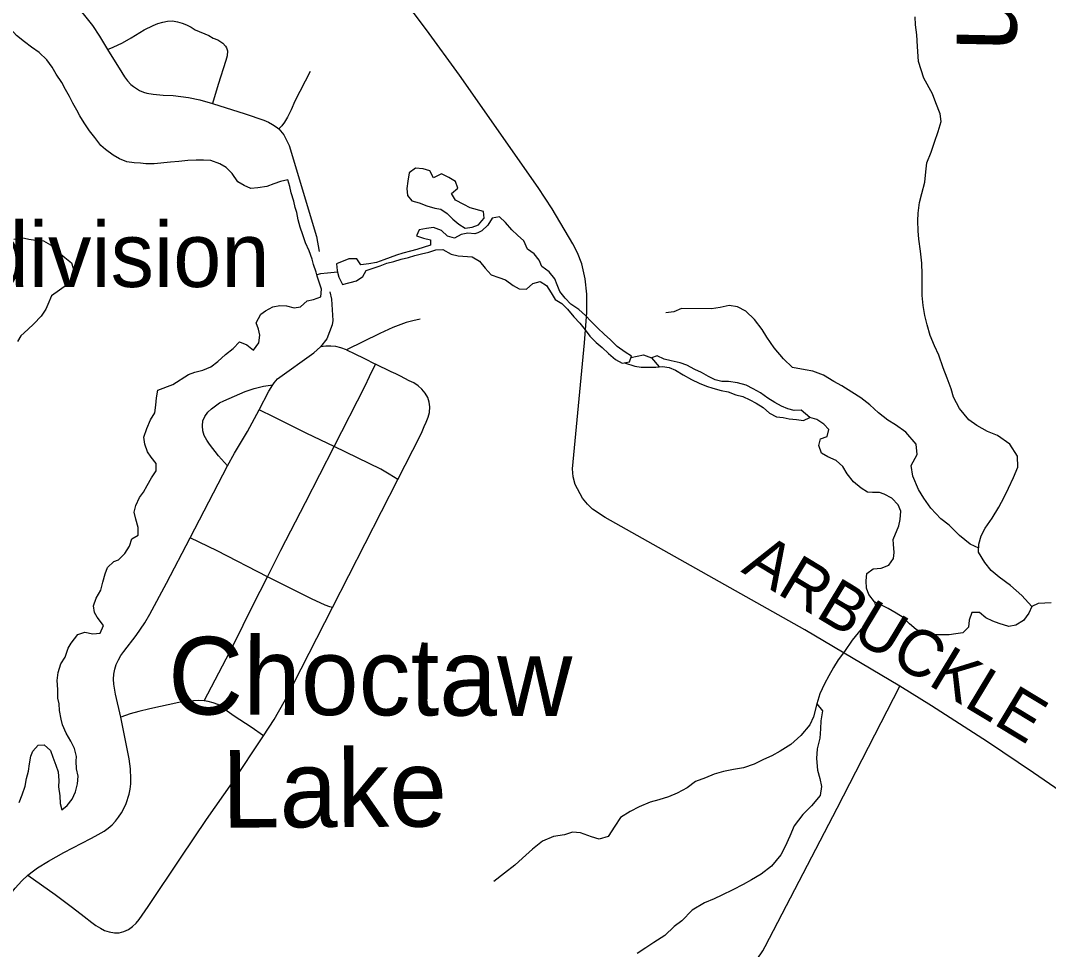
# Model space of a CAD drawing. Extents: x 0 to 36.5, y 0 to 25.3.
# Drawn here: x 5.198 to 6.451, y 18.689 to 19.822 of the extents above; entities that cross this region are included whole.
import ezdxf

# ---------------------------------------------------------------- set-up
doc = ezdxf.new("R2010")
doc.units = 0
for name, color, linetype in [('GM_X_County_Road', 7, 'Continuous'), ('GM_X_County_Road_Text', 7, 'Continuous'), ('GM_X_Major_Lake', 7, 'Continuous'), ('GM_X_Major_Lake_Text', 7, 'Continuous'), ('GM_X_Major_River', 7, 'Continuous'), ('GM_X_Minor_Lake', 7, 'Continuous'), ('GM_X_Minor_River', 7, 'Continuous'), ('GM_X_Minor_River_Text', 7, 'Continuous'), ('GM_X_Township_Road', 7, 'Continuous'), ('GM_X_Unincorporated_Text', 7, 'Continuous')]:
    doc.layers.add(name, color=color, linetype=linetype)

msp = doc.modelspace()

# ---------------------------------------------------------------- linework, layer by layer
at = {"layer": 'GM_X_County_Road'}
for points in [[(6.27, 19.0102), (6.154, 19.0787), (5.9106, 19.2156), (5.8953, 19.2261), (5.8889, 19.2321), (5.8831, 19.2395), (5.874, 19.2561), (5.8715, 19.2656), (5.8706, 19.2751), (5.8855, 19.4287), (5.8883, 19.4658), (5.8884, 19.4882), (5.8862, 19.5068), (5.882, 19.5251), (5.8767, 19.5387), (5.871, 19.5497), (5.8458, 19.5924), (5.8291, 19.6185), (5.7328, 19.7554), (5.6929, 19.8107), (5.6026, 19.9308)], [(6.4783, 18.8731), (6.4329, 18.9045), (6.3767, 18.9421), (6.3084, 18.9862), (6.27, 19.0102)]]:
    msp.add_lwpolyline(points, dxfattribs=at)
at = {"layer": 'GM_X_Major_Lake'}
for points in [[(5.3012, 19.6647), (5.2955, 19.6696), (5.2883, 19.6792), (5.2819, 19.6875), (5.2751, 19.6971), (5.2702, 19.7058), (5.2664, 19.7127), (5.2615, 19.7214), (5.2573, 19.7294), (5.2524, 19.7378), (5.2482, 19.7465), (5.2411, 19.7568), (5.2361, 19.7652), (5.2297, 19.7739), (5.2206, 19.7831), (5.2111, 19.7895), (5.2024, 19.796), (5.1929, 19.8036), (5.1858, 19.8116), (5.1824, 19.8174), (5.1771, 19.8257)], [(5.5237, 19.6276), (5.5145, 19.6258), (5.5066, 19.6227), (5.4982, 19.6197), (5.4872, 19.6178), (5.4784, 19.6171), (5.4705, 19.6206), (5.4625, 19.6251), (5.4557, 19.6354), (5.4485, 19.6426), (5.4409, 19.6472), (5.4299, 19.6514), (5.4208, 19.6518), (5.4117, 19.6515), (5.4018, 19.6511), (5.3908, 19.65), (5.3805, 19.6493), (5.3608, 19.6471), (5.3505, 19.6471), (5.3441, 19.6479), (5.3361, 19.6483), (5.3274, 19.6498), (5.3182, 19.6533), (5.3107, 19.6578), (5.3012, 19.6647)], [(5.5591, 19.5117), (5.5583, 19.5151), (5.5549, 19.5246), (5.5534, 19.531), (5.5496, 19.5413), (5.5451, 19.5508), (5.5421, 19.5607), (5.5387, 19.5698), (5.5364, 19.579), (5.5346, 19.5877), (5.5327, 19.5938), (5.5308, 19.6018), (5.5278, 19.6117), (5.5259, 19.6196), (5.5237, 19.6276)], [(5.1896, 19.5552), (5.1987, 19.5575), (5.2078, 19.5555), (5.2162, 19.554), (5.2257, 19.5532), (5.2344, 19.5486), (5.2423, 19.5406), (5.2518, 19.533), (5.2598, 19.5265), (5.2628, 19.517), (5.262, 19.5083), (5.2536, 19.4992), (5.2452, 19.4931), (5.2353, 19.4863), (5.2308, 19.4757), (5.2285, 19.47), (5.2227, 19.4613), (5.214, 19.4522), (5.2064, 19.445), (5.198, 19.4374), (5.1938, 19.4306)], [(5.2424, 19.0171), (5.2435, 19.0269), (5.247, 19.0372), (5.2523, 19.0455), (5.2558, 19.0566), (5.2596, 19.0626), (5.2676, 19.0732), (5.2763, 19.0759), (5.2858, 19.0739), (5.2949, 19.0747), (5.2988, 19.0842), (5.2912, 19.0941), (5.2878, 19.0998), (5.2867, 19.1081), (5.2901, 19.1173), (5.2958, 19.1271), (5.2982, 19.137), (5.3008, 19.1469), (5.3039, 19.1548), (5.3115, 19.162), (5.3172, 19.1643), (5.3248, 19.1719), (5.3306, 19.181), (5.3336, 19.1897), (5.3412, 19.1942), (5.3413, 19.2037), (5.3383, 19.2136), (5.3364, 19.2224), (5.3383, 19.2303), (5.3429, 19.2402), (5.3475, 19.2467), (5.3521, 19.255), (5.3574, 19.2641), (5.3631, 19.2728), (5.3631, 19.2816), (5.3571, 19.2896), (5.3525, 19.296), (5.3492, 19.3052), (5.348, 19.3139), (5.3519, 19.3245), (5.3561, 19.3348), (5.3614, 19.3435), (5.3626, 19.353), (5.3634, 19.3617), (5.3653, 19.3712), (5.3836, 19.378), (5.4026, 19.3901), (5.4102, 19.3931), (5.4201, 19.3954), (5.4299, 19.3995), (5.4383, 19.406), (5.4475, 19.4147), (5.457, 19.4219), (5.4646, 19.4302), (5.4737, 19.4264), (5.4817, 19.4199), (5.4881, 19.429), (5.4893, 19.4381), (5.4878, 19.4457), (5.4852, 19.4533), (5.4909, 19.464), (5.4966, 19.4678), (5.5054, 19.4727), (5.5137, 19.4745), (5.5221, 19.4741), (5.5312, 19.4715), (5.5392, 19.4726), (5.5472, 19.4802), (5.5548, 19.4817), (5.5639, 19.4851), (5.5647, 19.4945), (5.5628, 19.5006), (5.5598, 19.509), (5.5591, 19.5117)], [(5.196, 18.8682), (5.1998, 18.8774), (5.2032, 18.888), (5.2048, 18.8975), (5.2075, 18.9062), (5.2086, 18.9153), (5.2102, 18.9248), (5.2125, 18.9309), (5.219, 18.9381), (5.2266, 18.9385), (5.2341, 18.9316), (5.2371, 18.9236), (5.2409, 18.9137), (5.2436, 18.9054), (5.2443, 18.8951), (5.2439, 18.8871), (5.2457, 18.8761), (5.2461, 18.867), (5.248, 18.859), (5.2544, 18.8643), (5.2605, 18.8723), (5.2647, 18.881), (5.2671, 18.8909), (5.2678, 18.9004), (5.266, 18.9091), (5.2656, 18.9186), (5.266, 18.9243), (5.2634, 18.9342), (5.2589, 18.9429), (5.2532, 18.9528), (5.2487, 18.9627), (5.2472, 18.9696), (5.2453, 18.9802), (5.2446, 18.9886), (5.2431, 18.9954), (5.2431, 19.0061), (5.2424, 19.0171)]]:
    msp.add_lwpolyline(points, dxfattribs=at)
at = {"layer": 'GM_X_Major_River'}
for points in [[(5.5843, 19.5152), (5.586, 19.5089), (5.5905, 19.5002), (5.6073, 19.5047), (5.6152, 19.5096), (5.6191, 19.5172), (5.6362, 19.5228), (5.6442, 19.5259), (5.6529, 19.5281), (5.662, 19.5308), (5.6708, 19.533), (5.6787, 19.5353), (5.6867, 19.5375), (5.6955, 19.5394), (5.7042, 19.5424), (5.7126, 19.5428), (5.7228, 19.5371), (5.7315, 19.5351), (5.7483, 19.5336), (5.7574, 19.5286), (5.7642, 19.5198), (5.7714, 19.5118), (5.7808, 19.5084), (5.7892, 19.5057), (5.7983, 19.4989), (5.8059, 19.4947), (5.8146, 19.4943), (5.8222, 19.5014), (5.8313, 19.5037), (5.8389, 19.4987), (5.8446, 19.49), (5.8495, 19.4816), (5.8579, 19.4767), (5.8647, 19.4698), (5.8722, 19.4607), (5.8798, 19.4527), (5.8863, 19.4447), (5.8919, 19.4371), (5.8995, 19.4294), (5.9071, 19.423), (5.9147, 19.4157), (5.9234, 19.4085), (5.9313, 19.4039), (5.9401, 19.4058), (5.9428, 19.4126), (5.9348, 19.4176), (5.9253, 19.4244), (5.917, 19.4324), (5.9094, 19.4393), (5.9018, 19.4469), (5.8935, 19.4549), (5.8867, 19.4621), (5.8783, 19.4694), (5.8689, 19.4759), (5.8617, 19.4835), (5.8552, 19.4915), (5.8522, 19.4995), (5.8492, 19.5071), (5.8424, 19.5155), (5.8333, 19.5219), (5.8303, 19.5299), (5.8242, 19.5375), (5.8159, 19.5433), (5.8114, 19.5531), (5.8038, 19.5604), (5.7966, 19.5669), (5.789, 19.5756), (5.7818, 19.5825), (5.7727, 19.581), (5.7674, 19.5726), (5.7601, 19.5654), (5.7552, 19.5632)], [(5.7552, 19.5632), (5.7517, 19.5617), (5.743, 19.5625), (5.735, 19.561), (5.727, 19.5564), (5.7183, 19.5591), (5.7111, 19.566), (5.7013, 19.5694), (5.6929, 19.5683), (5.6838, 19.5668), (5.6807, 19.5592), (5.6891, 19.5565), (5.6978, 19.5546), (5.6978, 19.5481), (5.681, 19.5429), (5.6731, 19.5406), (5.6639, 19.5383), (5.656, 19.5357), (5.6484, 19.5331), (5.6407, 19.5301), (5.6316, 19.527), (5.6225, 19.5252), (5.6126, 19.5241), (5.6077, 19.5313), (5.5982, 19.5313), (5.583, 19.5253)], [(5.583, 19.5253), (5.5837, 19.5173), (5.5843, 19.5152)], [(5.5843, 19.5152), (5.572, 19.5139), (5.5636, 19.5132), (5.5591, 19.5117)], [(5.9341, 19.4045), (5.9469, 19.4004), (5.9545, 19.3993), (5.9723, 19.3992), (5.9763, 19.3996)], [(5.9421, 19.4109), (5.9572, 19.4141), (5.9671, 19.4106)], [(6.1602, 19.3379), (6.1496, 19.3467), (6.1412, 19.3463), (6.1332, 19.3482), (6.1257, 19.3517), (6.1173, 19.3559), (6.109, 19.3612), (6.0999, 19.3677), (6.0912, 19.3727), (6.0824, 19.3773), (6.0718, 19.3799), (6.0612, 19.3815), (6.0528, 19.3819), (6.0448, 19.3838), (6.0365, 19.388), (6.0282, 19.3926), (6.0198, 19.3964), (6.0103, 19.4018), (6.002, 19.4045), (5.991, 19.4068), (5.9826, 19.4091), (5.9739, 19.4129), (5.9671, 19.4106), (5.9763, 19.3996)], [(5.9763, 19.3996), (5.9807, 19.4), (5.9887, 19.3988), (5.9963, 19.3954), (6.0057, 19.39), (6.016, 19.3843), (6.0251, 19.3797), (6.0342, 19.3759), (6.0418, 19.3736), (6.052, 19.3709), (6.0604, 19.369), (6.0699, 19.3655), (6.0786, 19.3636), (6.0869, 19.3594), (6.0949, 19.3552), (6.1032, 19.3498), (6.1108, 19.343), (6.1195, 19.3384), (6.1275, 19.3376), (6.1351, 19.3361), (6.1438, 19.3353), (6.1526, 19.3341), (6.1602, 19.3379)], [(6.2321, 19.1219), (6.2291, 19.1295), (6.2287, 19.1386), (6.2295, 19.1474), (6.2375, 19.153), (6.247, 19.1538), (6.2565, 19.1575), (6.2622, 19.1659), (6.263, 19.1731), (6.2623, 19.1834), (6.2619, 19.1891), (6.2688, 19.2058), (6.2704, 19.2134), (6.2711, 19.2236), (6.2681, 19.2312), (6.2602, 19.2392), (6.2507, 19.2442), (6.245, 19.2461), (6.2366, 19.2461), (6.2306, 19.2469), (6.2226, 19.2515), (6.2135, 19.2595), (6.2059, 19.269), (6.2003, 19.2781), (6.1923, 19.2854), (6.1821, 19.29), (6.1745, 19.2942), (6.1711, 19.3037), (6.173, 19.3117), (6.1814, 19.3147), (6.1833, 19.323), (6.1772, 19.3295), (6.1689, 19.3352), (6.1602, 19.3379)], [(6.4543, 19.1118), (6.4467, 19.1114), (6.4387, 19.1107), (6.4307, 19.1073), (6.4273, 19.0993), (6.4208, 19.0902), (6.4113, 19.0845), (6.4029, 19.083), (6.3911, 19.0865), (6.3832, 19.0895), (6.3748, 19.0934), (6.3669, 19.0999), (6.3578, 19.0999), (6.3543, 19.0904), (6.3535, 19.082), (6.3467, 19.0752), (6.3383, 19.0737), (6.33, 19.0726), (6.3163, 19.0726), (6.3079, 19.0727), (6.3, 19.0731), (6.2897, 19.0792), (6.2818, 19.086), (6.2738, 19.094), (6.2655, 19.099), (6.2556, 19.1047), (6.2389, 19.1131), (6.2321, 19.1219)]]:
    msp.add_lwpolyline(points, dxfattribs=at)
at = {"layer": 'GM_X_Minor_Lake'}
for points in [[(5.7603, 19.5775), (5.7632, 19.581), (5.7621, 19.589), (5.7461, 19.5936), (5.7382, 19.5978), (5.7283, 19.6031), (5.7234, 19.6111), (5.731, 19.6176), (5.728, 19.6256), (5.72, 19.6305), (5.7109, 19.6351), (5.7014, 19.6302), (5.6969, 19.6386), (5.6885, 19.6412), (5.6794, 19.642), (5.6714, 19.6363)], [(5.6714, 19.6363), (5.6699, 19.6261), (5.6687, 19.617), (5.6695, 19.6086), (5.6748, 19.6021), (5.6839, 19.5995), (5.693, 19.596), (5.7028, 19.5933), (5.7104, 19.5918), (5.718, 19.5865), (5.7248, 19.5796), (5.732, 19.5735), (5.74, 19.5689), (5.7484, 19.57), (5.7563, 19.5727), (5.7603, 19.5775)]]:
    msp.add_lwpolyline(points, dxfattribs=at)
at = {"layer": 'GM_X_Minor_River'}
for points in [[(6.4307, 19.1073), (6.4186, 19.1206), (6.405, 19.1328), (6.3909, 19.1431), (6.3815, 19.1511), (6.3735, 19.161), (6.366, 19.1736), (6.3664, 19.1834), (6.369, 19.1933), (6.374, 19.2028), (6.3824, 19.2149), (6.3908, 19.2286), (6.3973, 19.2407), (6.4023, 19.2514), (6.4084, 19.2646), (6.4137, 19.2772), (6.4134, 19.2908), (6.4039, 19.3053), (6.3892, 19.316), (6.377, 19.3206), (6.3637, 19.3282), (6.3539, 19.3351), (6.3425, 19.3488), (6.3354, 19.3625), (6.3327, 19.3728), (6.3278, 19.3857), (6.3229, 19.3982), (6.3176, 19.4138), (6.3124, 19.4253), (6.3071, 19.4378), (6.3033, 19.4507), (6.3003, 19.4621), (6.2984, 19.4743), (6.2973, 19.4868), (6.297, 19.5017), (6.297, 19.5127), (6.2967, 19.526), (6.2952, 19.5408), (6.293, 19.5552), (6.2923, 19.5655), (6.2919, 19.5777), (6.2923, 19.5872), (6.2939, 19.6001), (6.2966, 19.6111), (6.3004, 19.6248), (6.3016, 19.6373), (6.3027, 19.6483), (6.3081, 19.6616), (6.3123, 19.6737), (6.3165, 19.6866), (6.3204, 19.6988), (6.3193, 19.7083), (6.314, 19.7216), (6.3098, 19.7326), (6.2992, 19.7517), (6.2959, 19.7619), (6.2928, 19.7722), (6.2914, 19.7904), (6.2907, 19.8045), (6.2892, 19.8167), (6.2888, 19.8265)], [(6.3661, 19.1782), (6.3557, 19.1831), (6.3425, 19.1938), (6.33, 19.2063), (6.3201, 19.214), (6.3076, 19.2273), (6.2993, 19.2395), (6.2925, 19.2498), (6.2857, 19.2661), (6.2838, 19.2791), (6.2911, 19.2927), (6.29, 19.3053), (6.2771, 19.3197), (6.2646, 19.3289), (6.2551, 19.3346), (6.2438, 19.3434), (6.2335, 19.3533), (6.2222, 19.3617), (6.2112, 19.3685), (6.199, 19.3766), (6.1896, 19.3815), (6.177, 19.3895), (6.1638, 19.3945), (6.1543, 19.3961), (6.1391, 19.3988), (6.1281, 19.4094), (6.1167, 19.4228), (6.1077, 19.4357), (6.102, 19.4452), (6.0929, 19.4574), (6.0823, 19.4673), (6.0721, 19.4727), (6.0618, 19.4746), (6.0508, 19.4719), (6.0402, 19.4705), (6.0037, 19.4706), (5.9942, 19.4668), (5.9847, 19.4653)], [(6.2389, 19.1131), (6.2419, 19.1006), (6.2316, 19.0888), (6.2229, 19.0794), (6.2118, 19.0661), (6.2023, 19.0524), (6.1947, 19.0422), (6.1889, 19.0327), (6.1832, 19.0225), (6.1782, 19.013), (6.1725, 19.0005), (6.1687, 18.9883), (6.1648, 18.9727), (6.1602, 18.9629), (6.1492, 18.95), (6.137, 18.939), (6.1241, 18.9307), (6.1138, 18.925), (6.1035, 18.9205), (6.0921, 18.9148), (6.0792, 18.9103), (6.067, 18.9084), (6.0549, 18.9058), (6.0435, 18.9028), (6.0328, 18.8983), (6.0206, 18.8937), (6.0104, 18.8862), (5.9986, 18.8797), (5.9879, 18.8752), (5.9761, 18.8714), (5.9655, 18.8684), (5.9522, 18.8628), (5.9411, 18.8571), (5.9294, 18.8499), (5.9225, 18.8393), (5.9141, 18.8268), (5.9034, 18.8234), (5.894, 18.8261), (5.8807, 18.831), (5.8708, 18.8318), (5.8609, 18.8288), (5.8476, 18.8266), (5.8343, 18.8209), (5.8221, 18.8114), (5.8099, 18.8004), (5.8004, 18.7917), (5.7879, 18.7819), (5.7749, 18.7717)], [(6.1687, 18.9883), (6.1755, 18.9799), (6.1735, 18.9678), (6.1731, 18.9579), (6.1723, 18.9465), (6.1693, 18.9336), (6.1685, 18.9218), (6.1696, 18.9074), (6.1722, 18.8975), (6.1744, 18.8876), (6.1729, 18.8766), (6.1622, 18.8641), (6.1516, 18.8535), (6.1409, 18.8398), (6.1359, 18.8269), (6.1302, 18.8144), (6.1248, 18.8041), (6.1134, 18.7905), (6.1008, 18.7806), (6.089, 18.7738), (6.0788, 18.7682), (6.0662, 18.7617), (6.0529, 18.7549), (6.0434, 18.7508), (6.0316, 18.7459), (6.0168, 18.7368), (6.0042, 18.7239), (5.9947, 18.7167), (5.9832, 18.7057), (5.9699, 18.6974), (5.96, 18.691), (5.9498, 18.6838)]]:
    msp.add_lwpolyline(points, dxfattribs=at)
at = {"layer": 'GM_X_Township_Road'}
for p, q in [((5.4045, 19.1912), (5.45, 19.2788)), ((5.578, 19.1059), (5.6578, 19.262))]:
    msp.add_line(p, q, dxfattribs=at)
for points in [[(5.241, 19.8633), (5.2616, 19.8441), (5.266, 19.8397), (5.2742, 19.8304), (5.2854, 19.8158), (5.2939, 19.803), (5.3039, 19.7868)], [(5.3039, 19.7868), (5.3108, 19.7895), (5.3219, 19.7948), (5.3328, 19.8008), (5.3485, 19.8105), (5.3594, 19.8161), (5.3652, 19.8184), (5.3711, 19.8201), (5.3771, 19.8211), (5.3832, 19.8216), (5.3891, 19.8206), (5.3948, 19.8189), (5.4002, 19.8166), (5.4057, 19.8138), (5.4108, 19.8107), (5.4275, 19.8037), (5.4327, 19.8005), (5.4384, 19.7983), (5.4442, 19.7946), (5.4478, 19.7907), (5.4488, 19.7888), (5.4499, 19.785), (5.4496, 19.779), (5.4481, 19.7732), (5.4385, 19.7441), (5.4318, 19.721)], [(5.3039, 19.7868), (5.3214, 19.7587), (5.3244, 19.7533), (5.328, 19.7485), (5.3322, 19.7441), (5.3353, 19.7415), (5.3429, 19.7366), (5.3477, 19.7346), (5.3515, 19.7335), (5.3596, 19.7321), (5.3718, 19.7311), (5.384, 19.7304), (5.4024, 19.7283), (5.4163, 19.7254), (5.4318, 19.721)], [(5.5507, 19.7597), (5.5323, 19.7238), (5.5278, 19.7132), (5.5233, 19.704), (5.5197, 19.698), (5.5163, 19.6934), (5.5127, 19.6898)], [(5.4318, 19.721), (5.4717, 19.7083), (5.4945, 19.7003), (5.5002, 19.6979), (5.505, 19.6954), (5.5095, 19.6924), (5.5127, 19.6898)], [(5.5127, 19.6898), (5.5189, 19.6828), (5.5252, 19.6696), (5.5586, 19.5585), (5.5619, 19.5402)], [(5.5747, 19.4909), (5.5769, 19.4822), (5.5784, 19.4561), (5.5777, 19.451), (5.5712, 19.4338), (5.5634, 19.4239)], [(5.685, 19.4578), (5.676, 19.4559), (5.6679, 19.4535), (5.6516, 19.4474), (5.6357, 19.4402), (5.595, 19.4205)], [(5.5052, 19.3775), (5.5071, 19.3802), (5.5111, 19.3848), (5.5553, 19.4167), (5.5634, 19.4239)], [(5.595, 19.4205), (5.5883, 19.4229), (5.5823, 19.4244), (5.5761, 19.425), (5.57, 19.4249), (5.5634, 19.4239)], [(5.595, 19.4205), (5.6052, 19.4153), (5.6165, 19.4102), (5.6307, 19.403)], [(5.58, 19.3025), (5.618, 19.3765), (5.6231, 19.3877), (5.6307, 19.403)], [(5.6578, 19.262), (5.6849, 19.3153), (5.6876, 19.3209), (5.6898, 19.3267), (5.6925, 19.3322), (5.6947, 19.338), (5.6962, 19.344), (5.6967, 19.3507), (5.6961, 19.3563), (5.6942, 19.3622), (5.6911, 19.3676), (5.6872, 19.3724), (5.6825, 19.3765), (5.6773, 19.3799), (5.6717, 19.3825), (5.6609, 19.3884), (5.6553, 19.3911), (5.6495, 19.3933), (5.6307, 19.403)], [(5.45, 19.2788), (5.4392, 19.291), (5.4283, 19.3052), (5.4247, 19.3102), (5.4218, 19.3157), (5.4199, 19.3215), (5.4194, 19.3275), (5.4201, 19.3336), (5.4224, 19.3391), (5.426, 19.3441), (5.4305, 19.3482), (5.4405, 19.3556), (5.4454, 19.3583), (5.4718, 19.3694), (5.4826, 19.3731), (5.4938, 19.376), (5.5052, 19.3775)], [(5.4887, 19.347), (5.5003, 19.3698), (5.5052, 19.3775)], [(5.45, 19.2788), (5.4585, 19.2943), (5.4744, 19.3207), (5.4887, 19.347)], [(5.58, 19.3025), (5.5467, 19.3184), (5.5071, 19.3382), (5.4887, 19.347)], [(5.4989, 19.1436), (5.5152, 19.1759), (5.5452, 19.2342), (5.58, 19.3025)], [(5.6578, 19.262), (5.6474, 19.2688), (5.6369, 19.2746), (5.58, 19.3025)], [(5.3198, 18.9722), (5.3133, 19.0001), (5.3114, 19.0125), (5.3111, 19.0185), (5.3115, 19.0246), (5.3126, 19.0307), (5.3143, 19.0366), (5.3171, 19.0421), (5.3201, 19.0474), (5.3235, 19.0525), (5.3387, 19.0719), (5.3492, 19.0872), (5.3553, 19.0979), (5.3757, 19.1359), (5.4045, 19.1912)], [(5.4989, 19.1436), (5.4374, 19.1752), (5.4045, 19.1912)], [(5.4217, 18.992), (5.4572, 19.0604), (5.481, 19.1083), (5.4989, 19.1436)], [(5.578, 19.1059), (5.5749, 19.1067), (5.5692, 19.109), (5.5524, 19.1167), (5.4989, 19.1436)], [(5.4941, 18.9494), (5.5071, 18.9695), (5.5193, 18.991), (5.5307, 19.0129), (5.578, 19.1059)], [(5.839, 18.2001), (5.8404, 18.2066), (5.8421, 18.2123), (5.8473, 18.2238), (5.8562, 18.24), (5.8814, 18.2884), (5.9354, 18.394), (5.9546, 18.4329), (6.0031, 18.5331), (6.0349, 18.6002), (6.0403, 18.6113), (6.0465, 18.6221), (6.0535, 18.6323), (6.0574, 18.6371), (6.0839, 18.6632), (6.0922, 18.6722), (6.096, 18.677), (6.1027, 18.6872), (6.1058, 18.6925), (6.1934, 18.8612), (6.27, 19.0102)], [(5.4217, 18.992), (5.4145, 18.9924), (5.4085, 18.9923), (5.4027, 18.9918), (5.3907, 18.99), (5.3552, 18.9823), (5.342, 18.9792), (5.3314, 18.9762), (5.3198, 18.9722)], [(5.4941, 18.9494), (5.479, 18.9601), (5.4583, 18.9734), (5.4382, 18.9876), (5.4325, 18.9898), (5.4266, 18.9913), (5.4217, 18.992)], [(5.2064, 18.7794), (5.2133, 18.7849), (5.2184, 18.7884), (5.2316, 18.7966), (5.2505, 18.807), (5.2833, 18.8244), (5.2889, 18.8271), (5.2996, 18.8333), (5.3046, 18.8369), (5.3093, 18.8409), (5.3135, 18.8455), (5.3173, 18.8504), (5.3207, 18.8556), (5.3237, 18.861), (5.3263, 18.8669), (5.33, 18.8785), (5.3312, 18.8846), (5.332, 18.8908), (5.3323, 18.8969), (5.3318, 18.9092), (5.3302, 18.9215), (5.3198, 18.9722)], [(5.2064, 18.7794), (5.2398, 18.756), (5.2609, 18.7402), (5.2751, 18.7289), (5.2847, 18.7216), (5.2896, 18.718), (5.295, 18.7147), (5.3002, 18.7121), (5.3059, 18.7102), (5.3122, 18.7091), (5.3178, 18.7093), (5.3238, 18.7107), (5.3292, 18.7132), (5.3343, 18.7167), (5.3385, 18.721), (5.3425, 18.7255), (5.3462, 18.7305), (5.3532, 18.7414), (5.3935, 18.8014), (5.4246, 18.8472), (5.456, 18.8925), (5.4941, 18.9494)], [(4.9088, 18.386), (4.9117, 18.3921), (4.9148, 18.3975), (4.9218, 18.4077), (4.9336, 18.4221), (4.9481, 18.4422), (4.9777, 18.482), (5.034, 18.556), (5.0983, 18.6416), (5.1327, 18.6859), (5.1756, 18.7442), (5.191, 18.7636), (5.1993, 18.7727), (5.2064, 18.7794)]]:
    msp.add_lwpolyline(points, dxfattribs=at)

# ---------------------------------------------------------------- texts
at = {"layer": 'GM_X_County_Road_Text'}
msp.add_text('ARBUCKLE', height=0.05682, rotation=328.8834, dxfattribs=at).set_placement((6.0752, 19.15))
at = {"layer": 'GM_X_Major_Lake_Text'}
for s, rotation, p in [('Choctaw', 359.7505, (5.3775, 18.9757)), ('Lake', 0.3056, (5.4434, 18.8374))]:
    msp.add_text(s, height=0.09469, rotation=rotation, dxfattribs=at).set_placement(p)
at = {"layer": 'GM_X_Minor_River_Text'}
msp.add_text('Ditch', height=0.09469, rotation=268.8281, dxfattribs=at).set_placement((6.3449, 20.0739))
at = {"layer": 'GM_X_Unincorporated_Text'}
msp.add_text('Choctaw Lake Subdivision', height=0.078977, rotation=0, dxfattribs=at).set_placement((4.2626, 19.497))

doc.saveas('drawing.dxf')
